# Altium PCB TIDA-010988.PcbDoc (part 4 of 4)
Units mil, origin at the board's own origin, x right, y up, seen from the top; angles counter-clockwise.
Board outline 3937.01 x 2559.06 mil, 4 copper layers (Top Layer, GND1, GND2, Bottom Layer), stack 61.6 mil thick; 270 components, 141 nets, 796 pads, 474 vias.
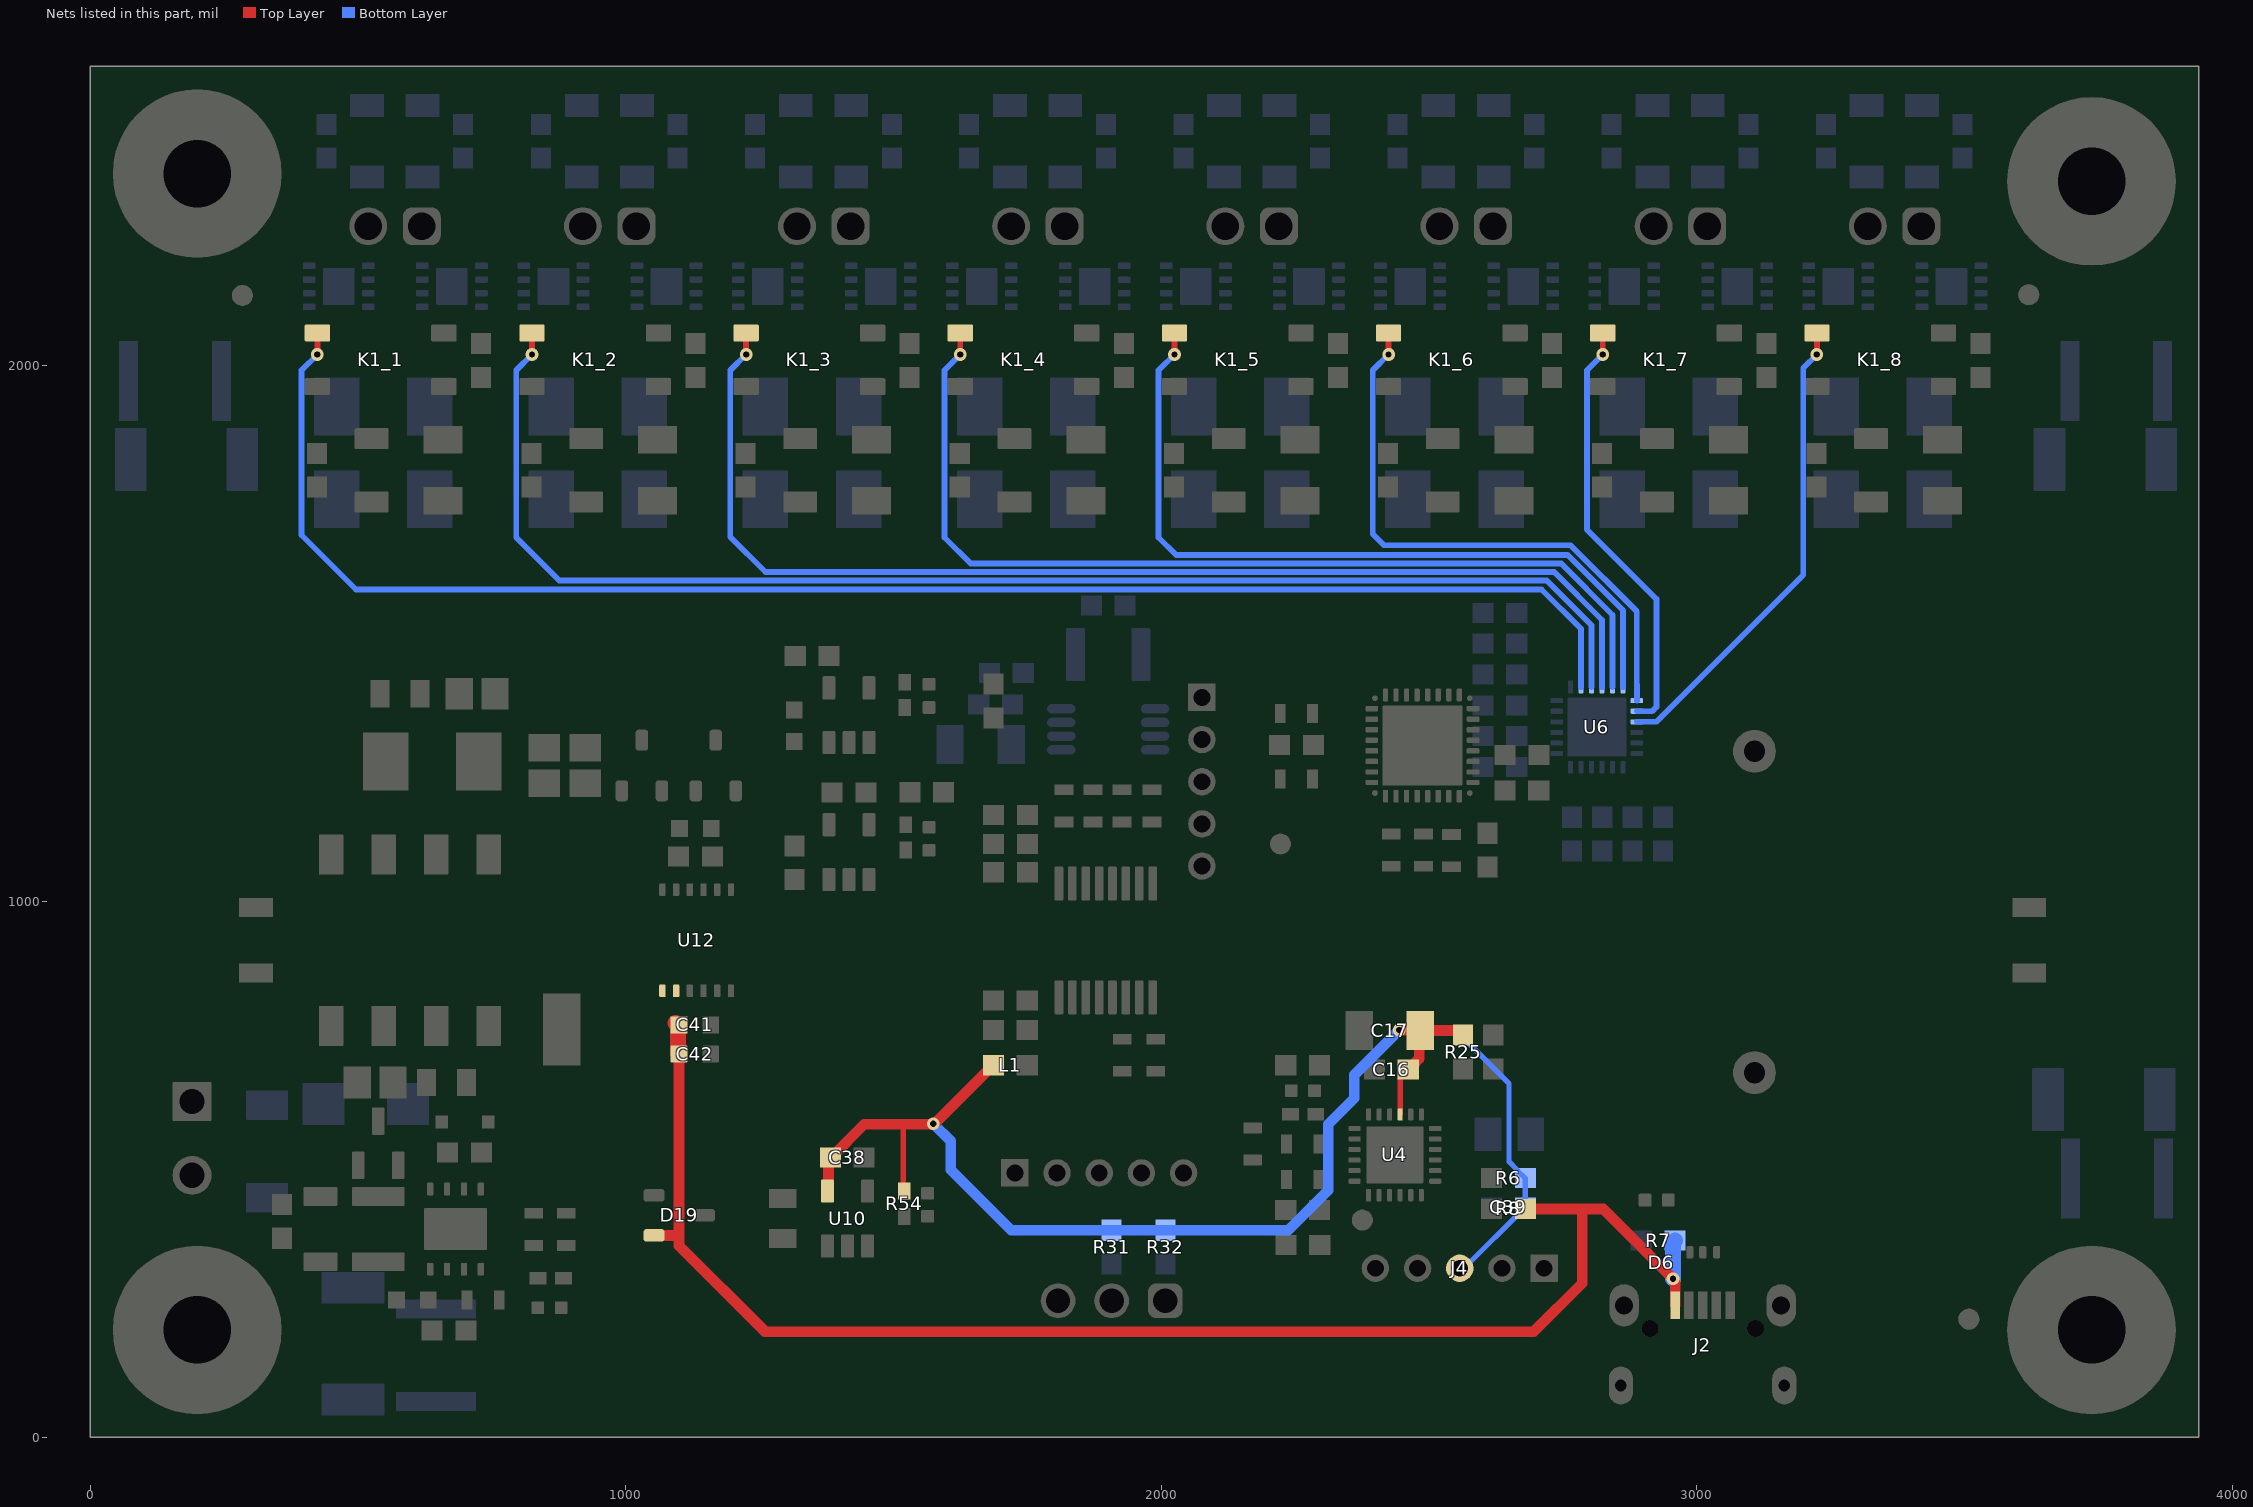
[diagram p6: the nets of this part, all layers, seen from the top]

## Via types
v1: diameter 23.62, hole 11.81, Top Layer to Bottom Layer, tented both sides, 374 vias
v2: diameter 19.68, hole 7.87, Top Layer to Bottom Layer, tented top, 64 vias
v3: diameter 19.68, hole 7.87, Top Layer to Bottom Layer, tented both sides, 26 vias
v4: diameter 19.68, hole 7.87, Top Layer to Bottom Layer, 9 vias
v5: diameter 28, hole 12, Top Layer to Bottom Layer, tented both sides, 1 vias

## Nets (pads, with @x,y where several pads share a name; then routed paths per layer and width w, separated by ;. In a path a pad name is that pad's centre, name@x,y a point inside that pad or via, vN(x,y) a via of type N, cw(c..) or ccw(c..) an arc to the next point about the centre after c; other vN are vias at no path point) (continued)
V/I_CTRL_1: K1_1.1 U6.20 | length 2959.5
  Top Layer w10.82: v1(424.4,2021.14) K1_1.1@424.4,2061.39
  Bottom Layer w10.82: v1(424.4,2021.14) 394.9,1991.64 394.9,1684.08 496.31,1582.67 2710.05,1582.67 2783.68,1509.04 U6.20@2783.68,1400.39
V/I_CTRL_2: K1_2.1 U6.21 | length 2585
  Top Layer w10.82: v1(825.02,2021.14) K1_2.1@825.02,2061.39
  Bottom Layer w10.82: v1(825.02,2021.14) 795.52,1991.64 795.52,1679.56 875.9,1599.18 2719.75,1599.18 2803.37,1515.56 U6.21@2803.37,1400.39
V/I_CTRL_3: K1_3.1 U6.22 | length 2210.1
  Top Layer w10.82: v1(1224.88,2021.14) K1_3.1@1224.88,2061.39
  Bottom Layer w10.82: v1(1224.88,2021.14) 1195.38,1991.64 1195.38,1680.53 1260.91,1615 2733.59,1615 2823.05,1525.54 U6.22@2823.05,1400.39
V/I_CTRL_4: K1_4.1 U6.23 | length 1836
  Top Layer w10.82: v1(1624.74,2021.14) K1_4.1@1624.74,2061.39
  Bottom Layer w10.82: v1(1624.74,2021.14) 1595.24,1991.64 1595.24,1679.74 1644.16,1630.82 2746.97,1630.82 2842.74,1535.05 U6.23@2842.74,1400.39
V/I_CTRL_5: K1_5.1 U6.24 | length 1460.6
  Top Layer w10.82: v1(2024.61,2021.14) K1_5.1@2024.61,2061.39
  Bottom Layer w10.82: v1(2024.61,2021.14) 1995.1,1991.64 1995.1,1679.41 2027.87,1646.64 2758.77,1646.64 2862.42,1542.99 U6.24@2862.42,1400.39
V/I_CTRL_6: K1_6.1 U6.1 | length 1103
  Top Layer w10.82: v1(2424.47,2021.14) K1_6.1@2424.47,2061.39
  Bottom Layer w10.82: v1(2424.47,2021.14) 2394.97,1991.64 2394.97,1685.91 2415.72,1665.16 2760.06,1665.16 ; 2764.26,1665.16 2887.82,1541.61 2887.82,1405.09 2888.01,1404.89 U6.1@2888.01,1374.8
V/I_CTRL_7: K1_7.1 U6.2 | length 804
  Top Layer w10.82: v1(2824.33,2021.14) K1_7.1@2824.33,2061.39
  Bottom Layer w10.82: v1(2824.33,2021.14) 2794.83,1991.64 2794.83,1694.2 2924.43,1564.59 2924.43,1363.01 2916.54,1355.12 U6.2@2888.01,1355.12
V/I_CTRL_8: K1_8.1 U6.3 | length 886.8
  Top Layer w10.82: v1(3224.19,2021.14) K1_8.1@3224.19,2061.39
  Bottom Layer w10.82: U6.3@2888.01,1335.43 2924.86,1335.43 3198.89,1609.46 3198.89,1995.84 v1(3224.19,2021.14)
VCC_3V3: C16.2 C17.2 C38.1 C39.1 J4.3 L1.1 R6.2 R25.1 R31.2 R32.2 R54.1 U4.3 U10.5 | length 2739.9
  Top Layer w10: R54.1@1517.97,459.18 1517.97,580.51 ; U4.3@2446.15,602.07 2446.15,671.95 C16.2@2460.14,685.94
  Top Layer w20: U10.5@1376.84,459.18 1378.65,460.99 C38.1@1378.65,517.89 ; C38.1@1382.2,521.67 1383.18,521.67 1445.71,584.2 1575.8,584.2 1685.78,694.17 L1.1@1686.76,694.17 ; v1(2444.46,759.99) 2492.38,759.99 C17.2@2493.4,758.98 ; C16.2@2460.14,685.94 C16.2@2460.81,686.62 ; C16.2@2470.81,695.63 2481.74,706.56 2481.74,747.33 C17.2@2493.4,758.98 ; R25.1@2563.63,750.28 2554.93,758.98 C17.2@2493.4,758.98
  Bottom Layer w10: v1(2444.46,759.99) 2549.34,759.99 2649.2,660.13 2649.2,514.11 2665.16,498.15 2665.16,497.17 2678.86,483.47 R6.2@2679.84,483.47 C39.1@2679.84,428.8 2678.86,428.8 2565.16,315.11 J4.3@2557.32,315.11
  Bottom Layer w20: v1(1574.47,585.12) 1606.88,552.71 1606.88,499.27 1720.07,386.08 R31.2@1907.36,386.08 R32.2@2007.75,386.08 2237.28,386.08 2311.98,460.79 2311.98,584.14 2360.48,632.64 2360.48,676.02 v1(2444.46,759.99)
VUSB: C41.2 C42.2 D6.2 D19.2 J2.1 R7.2 R8.2 U12.1 U12.2 | length 2857.5
  Top Layer w10: C41.2@1094.2,772.18 C41.2@1096.82,769.55
  Top Layer w15: v1(2955.37,295.75) 2955.37,293.42 v1@2959.62,289.17
  Top Layer w20: D19.2@1044.44,377.49 D19.2@1052.32,377.49 ; D19.2@1052.83,376.45 1098.74,376.45 1099.77,377.49 ; C42.2@1097.81,715.09 1099.77,713.12 1099.77,377.49 ; R8.2@2679.84,425.9 2786.03,425.9 ; v1(2955.37,295.75) 2825.23,425.9 2786.03,425.9 ; J2.1@2959.62,245.88 v1@2959.62,289.17 ; 1099.77,377.49 1099.77,357.05 1260,196.82 2695.72,196.82 2786.03,287.14 2786.03,425.9
  Top Layer w30: C41.2@1093.12,773.26 C41.2@1094.2,772.18 ; C41.2@1096.82,769.55 1097.81,769.55 C42.2@1097.81,715.09
  Bottom Layer w30: v1(2955.37,295.75) 2955.37,363.21 2959.07,366.91 R7.2@2959.25,366.91
pads on no net: D4.1S D4.2S D5.1S D5.2S D6.1S D6.2S D10.2 FID1.1 FID2.1 FID3.1 FID4.1 FID5.1 FID6.1 H5.0 H6.0 H7.0 H8.0 J2. LBL1.0 T1.2 T1.3 U1_1.9 U1_2.9 U1_3.9 U1_4.9 U1_5.9 U1_6.9 U1_7.9 U1_8.9 U2_1.9 U2_2.9 U2_3.9 U2_4.9 U2_5.9 U2_6.9 U2_7.9 U2_8.9 U4.11 U4.12 U4.13 U4.17 U6.4 U6.5 U6.6 U6.7 U6.8 U8.9@652.55,388.27 U8.9@712,388.27 U9.4 U10.3 U10.4 U11.3 U11.4
copper on no net:
  other v2: 464.53,2123.71 675.61,2123.71 865.15,2123.71 1076.23,2123.71 1265.01,2123.71 1476.09,2123.71 1664.87,2123.71 1875.95,2123.71 2064.73,2123.71 2275.82,2123.71 2464.59,2123.71 2675.68,2123.71 2864.45,2123.71 3075.54,2123.71 3264.32,2123.71 3475.4,2123.71 444.84,2148.32 484.21,2148.32 655.93,2148.32 695.3,2148.32 845.46,2148.32 884.83,2148.32 1056.55,2148.32 1095.92,2148.32 1245.32,2148.32 1284.69,2148.32 1456.41,2148.32 1495.78,2148.32 1645.19,2148.32 1684.56,2148.32 1856.27,2148.32 1895.64,2148.32 2045.05,2148.32 2084.42,2148.32 2256.13,2148.32 2295.5,2148.32 2444.91,2148.32 2484.28,2148.32 2655.99,2148.32 2695.36,2148.32 2844.77,2148.32 2884.14,2148.32 3055.85,2148.32 3095.22,2148.32 3244.63,2148.32 3284,2148.32 3455.72,2148.32 3495.09,2148.32 464.53,2172.93 675.61,2172.93 865.15,2172.92 1076.23,2172.92 1265.01,2172.92 1476.09,2172.92 1664.87,2172.92 1875.95,2172.92 2064.73,2172.92 2275.82,2172.92 2464.59,2172.92 2675.68,2172.92 2864.45,2172.92 3075.54,2172.92 3264.32,2172.92 3475.4,2172.92

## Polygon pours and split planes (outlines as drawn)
GND on Top Layer "TOP_LAYER_GND_P188" (solid, remove dead copper, pour order 188): 1150.98,1011.08 1100.2,1011.03 1049.51,1011.08 1049.51,1155.81 1121.25,1155.81 1121.37,1155.68 1121.37,1050.28 1137.55,1034.11 1151.31,1034.11
GND_0V on Top Layer "TOP_LAYER_GND_0V_P187" (solid, remove dead copper, pour order 187): 1113.9,845 1113.9,822.42 1113.87,822.39 1113.9,822.35 1113.9,805.3 1114.03,805.3 1124.93,794.4 1125.14,794.61 1140.58,794.61 1140.58,696.68 1140.43,696.53 1140.56,696.4 1181.79,696.4 1211.64,696.4 1211.64,844.91 1203.85,844.92
VUSB on Top Layer "TOP_LAYER_VUSB_P186" (solid, remove dead copper, pour order 186): 1099.95,844.87 1062.82,844.87 1062.67,845.02 1062.49,844.84 1062.49,695.23 1117.66,695.23 1117.66,787.67 1112.44,792.9 1100.09,805.25
NetD1_1_2 on Top Layer "TOP_LAYER_NETD1_1_2_P142" (solid, remove dead copper, pour order 142): 650.1,1858.84 648.89,1860.06 648.89,1976.62 749.09,1976.62 749.09,1896.19
NetD1_3_2 on Top Layer "TOP_LAYER_NETD1_3_2_P144" (solid, remove dead copper, pour order 144): 1450.58,1858.84 1449.37,1860.06 1449.37,1976.62 1549.57,1976.62 1549.57,1896.19
NetD1_8_2 on Top Layer "TOP_LAYER_NETD1_8_2_P149" (solid, remove dead copper, pour order 149): 3449.89,1858.84 3448.68,1860.06 3448.68,1976.62 3548.87,1976.62 3548.87,1896.19
NetD1_7_2 on Top Layer "TOP_LAYER_NETD1_7_2_P148" (solid, remove dead copper, pour order 148): 3050.03,1858.84 3048.81,1860.06 3048.81,1976.62 3149.01,1976.62 3149.01,1896.19
NetD1_6_2 on Top Layer "TOP_LAYER_NETD1_6_2_P147" (solid, remove dead copper, pour order 147): 2650.17,1858.84 2648.95,1860.06 2648.95,1976.62 2749.15,1976.62 2749.15,1896.19
NetD1_5_2 on Top Layer "TOP_LAYER_NETD1_5_2_P146" (solid, remove dead copper, pour order 146): 2250.31,1858.84 2249.09,1860.06 2249.09,1976.62 2349.29,1976.62 2349.29,1896.19
NetD1_4_2 on Top Layer "TOP_LAYER_NETD1_4_2_P145" (solid, remove dead copper, pour order 145): 1850.45,1858.84 1849.23,1860.06 1849.23,1976.62 1949.43,1976.62 1949.43,1896.19
NetD1_2_2 on Top Layer "TOP_LAYER_NETD1_2_2_P143" (solid, remove dead copper, pour order 143): 1050.72,1858.84 1049.51,1860.06 1049.51,1976.62 1149.7,1976.62 1149.7,1896.19
GND on Bottom Layer "BOTTOM_LAYER_GND_P190" (solid, remove dead copper, pour order 190): 3737.09,2050.14 3737.09,1774.96 3737.09,1765.76 3666.35,1765.76 3595.51,1765.76 3594.27,1765.76 3594.27,1769.02 3594.27,1777.29 3594.27,2049.84
GND_0V on Bottom Layer "BOTTOM_LAYER_GND_0V_P193" (solid, remove dead copper, pour order 193): 721.27,201.89 446.35,201.89 428.91,201.89 428.91,344.71 440.4,344.71 448.68,344.71 720.96,344.71
GND_0V on Bottom Layer "BOTTOM_LAYER_GND_0V_P192" (solid, remove dead copper, pour order 192): 3626.86,690.15 3626.86,414.64 3626.86,405.44 3697.6,405.44 3768.44,405.44 3769.68,405.44 3769.68,408.7 3769.68,416.97 3769.68,689.85
GND on Bottom Layer "BOTTOM_LAYER_GND_P191" (solid, remove dead copper, pour order 191): 204.2,2050.16 204.2,1774.96 204.2,1765.76 274.94,1765.76 345.78,1765.76 347.02,1765.76 347.02,1769.02 347.02,1777.29 347.02,2049.86
GND on Bottom Layer "BOTTOM_LAYER_GND_P150" (solid, remove dead copper, pour order 150): 415.91,2201.46 421.66,2195.71 421.67,2107.21 416.5,2102.04 379.59,2102.04 368.18,2116.64 368.18,2193.81 379.75,2201.39
GND on Bottom Layer "BOTTOM_LAYER_GND_P158" (solid, remove dead copper, pour order 158): 721.71,2103.98 715.95,2109.73 715.94,2198.22 721.12,2203.4 758.02,2203.4 771.4,2203.4 771.4,2190.01 771.4,2104.08 757.87,2104.05
GND on Bottom Layer "BOTTOM_LAYER_GND_P184" (solid, remove dead copper, pour order 184): 3215.5,2203.1 3221.25,2197.35 3221.26,2108.86 3216.09,2103.68 3179.19,2103.68 3167.77,2103.68 3167.77,2118.29 3167.77,2195.46 3167.77,2203.1 3179.34,2203.03
GND on Bottom Layer "BOTTOM_LAYER_GND_P183" (solid, remove dead copper, pour order 183): 3123.43,2103.86 3117.68,2109.62 3117.67,2198.11 3122.84,2203.28 3159.74,2203.28 3173.13,2203.28 3173.13,2189.9 3173.13,2117.47 3173.13,2103.86 3159.59,2103.94
GND on Bottom Layer "BOTTOM_LAYER_GND_P182" (solid, remove dead copper, pour order 182): 2815.64,2203.1 2821.39,2197.35 2821.4,2108.86 2816.23,2103.68 2779.32,2103.68 2767.91,2103.68 2767.91,2118.29 2767.91,2195.46 2767.91,2203.1 2779.48,2203.03
GND on Bottom Layer "BOTTOM_LAYER_GND_P181" (solid, remove dead copper, pour order 181): 2723.57,2103.86 2717.81,2109.62 2717.8,2198.11 2722.98,2203.28 2759.88,2203.28 2773.26,2203.28 2773.26,2189.9 2773.26,2117.47 2773.26,2103.86 2759.73,2103.94
GND on Bottom Layer "BOTTOM_LAYER_GND_P180" (solid, remove dead copper, pour order 180): 2415.78,2203.1 2421.53,2197.35 2421.54,2108.86 2416.37,2103.68 2379.46,2103.68 2368.05,2103.68 2368.05,2118.29 2368.05,2195.46 2368.05,2203.1 2379.62,2203.03
GND on Bottom Layer "BOTTOM_LAYER_GND_P179" (solid, remove dead copper, pour order 179): 2323.71,2103.86 2317.95,2109.62 2317.94,2198.11 2323.12,2203.28 2360.02,2203.28 2373.4,2203.28 2373.4,2189.9 2373.4,2117.47 2373.4,2103.86 2359.87,2103.94
GND on Bottom Layer "BOTTOM_LAYER_GND_P178" (solid, remove dead copper, pour order 178): 2015.92,2203.1 2021.67,2197.35 2021.68,2108.86 2016.51,2103.68 1979.6,2103.68 1968.19,2103.68 1968.19,2118.29 1968.19,2195.46 1968.19,2203.1 1979.76,2203.03
GND on Bottom Layer "BOTTOM_LAYER_GND_P177" (solid, remove dead copper, pour order 177): 1923.84,2103.86 1918.09,2109.62 1918.08,2198.11 1923.25,2203.28 1960.16,2203.28 1973.54,2203.28 1973.54,2189.9 1973.54,2117.47 1973.54,2103.86 1960.01,2103.94
GND on Bottom Layer "BOTTOM_LAYER_GND_P176" (solid, remove dead copper, pour order 176): 1616.06,2203.1 1621.81,2197.35 1621.82,2108.86 1616.65,2103.68 1579.74,2103.68 1568.33,2103.68 1568.33,2118.29 1568.33,2195.46 1568.33,2203.1 1579.89,2203.03
GND on Bottom Layer "BOTTOM_LAYER_GND_P175" (solid, remove dead copper, pour order 175): 1523.98,2103.86 1518.23,2109.62 1518.22,2198.11 1523.39,2203.28 1560.3,2203.28 1573.68,2203.28 1573.68,2189.9 1573.68,2117.47 1573.68,2103.86 1560.14,2103.94
GND on Bottom Layer "BOTTOM_LAYER_GND_P172" (solid, remove dead copper, pour order 172): 1216.19,2203.1 1221.95,2197.35 1221.96,2108.86 1216.78,2103.68 1179.88,2103.68 1168.47,2103.68 1168.47,2118.29 1168.47,2195.46 1168.47,2203.1 1180.03,2203.03
GND on Bottom Layer "BOTTOM_LAYER_GND_P171" (solid, remove dead copper, pour order 171): 820.53,2203.1 826.29,2197.35 826.3,2108.86 821.12,2103.68 784.22,2103.68 772.81,2103.68 741.02,2103.68 741.02,2161.33 741.02,2203.3 742.92,2203.1 772.81,2203.1 784.37,2203.03
GND on Bottom Layer "BOTTOM_LAYER_GND_P165" (solid, remove dead copper, pour order 165): 3520.32,2103.64 3514.57,2109.39 3514.56,2197.88 3519.73,2203.06 3556.63,2203.06 3570.02,2189.67 3570.02,2117.25 3556.48,2103.71
GND on Bottom Layer "BOTTOM_LAYER_GND_P159" (solid, remove dead copper, pour order 159): 1124.12,2103.86 1118.37,2109.62 1118.36,2198.11 1123.53,2203.28 1160.44,2203.28 1173.82,2203.28 1173.82,2189.9 1173.82,2117.47 1173.82,2103.86 1160.28,2103.94
GND on GND1 "GND1_GND_P167" (solid, remove dead copper, pour order 167): -3.37,972.72 -3.37,2553.11 3933.64,2553.11 3933.64,972.72
GND_0V on GND1 "GND1_GND_0V_P168" (solid, remove dead copper, pour order 168): 0,883.66 0,0 3937.01,0 3937.01,883.66
GND on GND2 "GND2_GND_P166" (solid, remove dead copper, pour order 166): 0,972.72 0,2559.06 3937.01,2559.06 3937.01,972.72
GND_0V on GND2 "GND2_GND_0V_P169" (solid, remove dead copper, pour order 169): -0.01,883.66 -0.01,-4 3937,-4 3937,883.66

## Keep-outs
Keep-Out Layer:
  text ".Layer_Name" at 132,-1764.01 h60

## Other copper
Top Layer:
  text ".Layer_Name" at 132,-1764.01 h60
Bottom Layer:
  text ".Layer_Name" at 132,-1764.01 h60

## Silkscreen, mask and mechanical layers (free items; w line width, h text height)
Top Overlay:
  lines w5: 2037,1445.84 2037,1446.25
  lines w8: 1586.46,190.64 1586.46,486.09 1657.68,486.09
  lines w10: 1641.21,502.3 1657.39,486.11 ; 1641.49,469.9 1657.68,486.09 ; 2020.78,1462.97 2036.97,1446.78 ; 2037,1445.84 2037,1654.07 ; 2037,1446.04 2037,1446.5 2053.19,1462.69
  text "A14" at 3094.45,2279.92 h30
  text "A10" at 703.23,2251.04 h30
  text "A8" at 1104.3,2251.08 h30
  text "A6" at 1504.42,2251.04 h30
  text "A4" at 1905.27,2251.06 h30
  text "A3" at 1995.82,2251.23 h30
  text "A2" at 2304.44,2251.1 h30
  text "A0" at 2704.16,2251.14 h30
  text "A15" at 2769.16,2251.71 h30
  text "A11" at 374.18,2250.96 h30
  text "A9" at 798.31,2250.96 h30
  text "A7" at 1192.94,2250.96 h30
  text "A5" at 1596.27,2250.89 h30
  text "A1" at 2399.24,2250.96 h30
  text "A13" at 3172.29,2243.59 h30
  text "A12" at 3494.87,2202.36 h30
  text "CSADC" at 2049.25,1608 h70
  text "SCLK" at 2049.25,1554.91 h70
  text "SDI" at 2049.25,1501.42 h70
  text "SDO" at 2054.3,1439.46 h70
  text "CS IO" at 2023.65,968.38 h70
  text "24V" at 139.91,715.09 h100
  text "CSADC" at 1597.33,396.74 h70
  text "GND" at 29.06,353.3 h70
  text "GND_0V" at 1597.33,343.71 h70
  text "SCLK" at 1597.33,276.91 h70
  text "PICO" at 1597.33,225.18 h70
  text "POCI" at 1597.33,172.22 h70
  text "RX" at 1878.46,140 h70
  text "TX" at 1977.83,140 h70
  text "RST" at 2747.33,110.96 h70 r90
  text "SWDIO" at 2424.65,60 h70 r90
  text "TIDA-010988.PCB_Rev" at 361.59,50 h108.27
  text "SWCLK" at 2500.3,46.65 h70 r90
  text "VCC3V3" at 2578.56,25.92 h70 r90
  text "GND_0V" at 2662.99,20 h70 r90
  text ".Layer_Name" at 132,-1764.01 h60
Bottom Overlay:
  text ".Layer_Name" at 132,-1764.01 h60
Top Paste:
  text ".Layer_Name" at 132,-1764.01 h60
Bottom Paste:
  text ".Layer_Name" at 132,-1764.01 h60
Top Solder:
  text ".Layer_Name" at 132,-1764.01 h60
  text ".Layer_Name" at 132,-1764.01 h60
Bottom Solder:
  text ".Layer_Name" at 132,-1764.01 h60
Drill Guide:
  text ".Layer_Name" at 132,-1764.01 h60
M1 Board Outline:
  the board outline again, w10
  text ".Layer_Name" at 132,-1764.01 h60
M2 Board Dimensions:
  rectangle: -445,-1180.51 -320,-1055.51
  rectangle: -320,-1305.51 55,-1180.51
  lines w7: -445,-1180.51 555,-1180.51 ; -320,-1305.51 -320,-1055.51 ; -195,-1305.51 -195,-1055.51 ; 55,-1305.51 55,-1055.51 ; 305,-1305.51 305,-1055.51 ; -445,-1305.51 555,-1305.51 555,-1055.51 -445,-1055.51 -445,-1305.51
  text ".Layer_Name" at 132,-1764.01 h60
M3 3D STEP Top:
  text ".Layer_Name" at 132,-1764.01 h60
M4 3D STEP Bottom:
  text ".Layer_Name" at 132,-1764.01 h60
M5 Assembly Top:
  lines w10: -737,-1835.68 5863,-1835.68 ; -737,-1632.35 5865,-1632.35 ; -737,-1429.01 -737,-2039.01 3268,-2039.01 5865,-2039.01 5865,-1429.01 -736.5,-1429.01 -736.5,-2039.01 839,-2039.01 ; 1728,-2039.01 1728,-1429.01 ; 2995,-1632.35 2995,-1429.01 ; 3835,-1632.35 3835,-1429.01 ; 4457,-2045.51 4457,-1842.68
  text "COMPONENTS MARKED 'DNP' SHOULD NOT BE POPULATED." at 708.5,-1224.01 h60
  text "ASSEMBLY VARIANT:" at 708,-1339.51 h60
  text ".VariantName" at 1744,-1339.51 h60
  text "PCB VIEWED FROM TOP SIDE" at -673.5,-1561.18 h60
  text "BOARD #:" at 1803,-1561.18 h60
  text ".PRJ_Number" at 2348.5,-1561.18 h60
  text "REV:" at 3193,-1561.18 h60
  text ".PCB_Rev" at 3484.5,-1561.18 h60
  text "SVN REV:" at 4031,-1561.18 h60
  text ".VersionControl_RevNumber" at 4537,-1561.18 h60
  text "TID #:" at 1803,-1764.51 h60
  text ".TID" at 2348.5,-1764.51 h60
  text "PLOT NAME =" at -673.5,-1969.85 h60
  text ".plot_File_Name" at 132,-1969.85 h60
  text "GENERATED    :" at 1805,-1969.85 h60
  text ".Print_Date" at 2674.5,-1969.85 h60
  text ".Print_Time" at 3403.5,-1969.85 h60
  text "TEXAS INSTRUMENTS" at 4668,-1969.85 h60
M6 Assembly Bottom:
  lines w10: -737.5,-1632.85 5864.5,-1632.85 ; -735.5,-1836.18 5864.5,-1836.18 ; 670.5,-2046.01 670.5,-1843.18 ; 1292.5,-1632.85 1292.5,-1429.51 ; 2132.5,-1632.85 2132.5,-1429.51 ; 3399.5,-2039.51 3399.5,-1429.51 ; 4288.5,-2039.51 5864,-2039.51 5864,-1429.51 -737.5,-1429.51 -737.5,-2039.51 1859.5,-2039.51 5864.5,-2039.51 5864.5,-1429.51
  text "COMPONENTS MARKED 'DNP' SHOULD NOT BE POPULATED." at 5657,-1223.51 h60
  text ".VariantName" at 4613,-1339.51 h60
  text "ASSEMBLY VARIANT:" at 5652,-1339.51 h60
  text ".VersionControl_RevNumber" at 590.5,-1561.68 h60
  text "SVN REV:" at 1096.5,-1561.68 h60
  text ".PCB_Rev" at 1643,-1561.68 h60
  text "REV:" at 1934.5,-1561.68 h60
  text ".PRJ_Number" at 2779,-1561.68 h60
  text "BOARD #:" at 3324.5,-1561.68 h60
  text "PCB VIEWED FROM BOTTOM SIDE" at 5801,-1561.68 h60
  text ".TID" at 2779,-1765.01 h60
  text "TID #:" at 3324.5,-1765.01 h60
  text "TEXAS INSTRUMENTS" at 459.5,-1970.35 h60
  text ".Print_Time" at 1724,-1970.35 h60
  text ".Print_Date" at 2453,-1970.35 h60
  text "GENERATED    :" at 3322.5,-1970.35 h60
  text ".plot_File_Name" at 4995.5,-1970.35 h60
  text "PLOT NAME =" at 5801,-1970.35 h60
M9 Title Sheet:
  drawing of 57 lines, arcs and shapes, not listed
  text "1" at 294.84,7130.99 h70
  text "2" at 2790.5,7130.99 h70
  text "3" at 5279.84,7130.99 h70
  text "4" at 7786.51,7130.99 h70
  text "5" at 10285.5,7130.99 h70
  text "6" at 12790.5,7130.99 h70
  text "A" at -861.5,5987.99 h70
  text "A" at 13938.5,5987.99 h70
  text "B" at -861.5,3607.99 h70
  text "B" at 13938.5,3607.99 h70
  text "C" at -861.5,1232.99 h70
  text "C" at 13938.5,1232.99 h70
  text "PROJECT TITLE:" at 10898.5,-628.01 h45
  text ".PRJ_Title" at 10948.5,-761.34 h70
  text "DESIGNED FOR:" at 10898.5,-929.01 h45
  text ".PRJ_Customer" at 10948.5,-1069.01 h70
  text "D" at -861.5,-1137.01 h70
  text "D" at 13938.5,-1137.01 h70
  text "FILE NAME:" at 10898.5,-1229.01 h45
  text ".PCB_File_Name_No_Path" at 10948.5,-1349.01 h70
  text "Texas Instruments (TI) and/or its licensors do not warrant the accuracy or completeness of this specification" at 5929,-1510.85 h45
  text "ENGINEER:" at 10898.5,-1519.01 h45
  text "LAYOUT BY:" at 12403.5,-1519.01 h45
  text "or any information contained therein. TI and/or its licensors do not warrant that this design will meet" at 5884.01,-1623.52 h45
  text ".PRJ_Engineer" at 10948.5,-1674 h70
  text ".PCB_Layout" at 12454,-1674 h70
  text "the specifications, will be suitable for your application or fit for any particular purpose, or will operate in" at 5884.01,-1736.18 h45
  text ".Layer_Name" at 132,-1764.01 h60
  text "ALTIUM DESIGNER VERSION:" at 12403.5,-1829.01 h45
  text "an implementation. TI and/or its licensors do not warrant that the design is production worthy. You should" at 5884.01,-1848.85 h45
  text "completely validate and test your design implementation to confirm the system functionality for your application." at 5929,-1961.51 h45
  text ".print_Scale" at 10948.5,-1962.34 h70
  text ".Application_BuildNumber" at 12454,-1962.34 h70
  text "1" at 294.84,-2169.01 h70
  text "2" at 2790.5,-2169.01 h70
  text "3" at 5279.84,-2169.01 h70
  text "4" at 7786.51,-2169.01 h70
  text "5" at 10285.5,-2169.01 h70
  text "6" at 12790.5,-2169.01 h70
M10 Fab Notes:
  drawing of 189 lines, arcs and shapes, not listed
  text "DESIGN INFORMATION" at 11937.02,5450.66 h60
  text "MIN. TRACK WIDTH:" at 11292.46,5318.54 h60
  text "8" at 12388.7,5318.54 h60
  text "MIL" at 12543.46,5318.54 h60
  text "7.874" at 12222.32,5196.85 h60
  text "MIN. CLEARANCE:" at 11292.46,5194.41 h60
  text "MIL" at 12543.46,5194.41 h60
  text "MIN. VIA PAD SIZE:" at 11292.46,5070.28 h60
  text "24" at 12358.71,5070.29 h60
  text "MIL" at 12543.46,5070.28 h60
  text "0.05mm (2MIL)" at 11987.46,4940.38 h60
  text "MINIMUM ANNULAR RING" at 10963.23,4932.16 h60
  text "EXTERNAL" at 12695.46,4932.16 h60
  text "PER" at 11163.23,4822.04 h60
  text "IPC-D-275 CLASS 2 LEVEL C" at 11383.23,4822.03 h60
  text "MIL, HOLES" at 12871.46,4721.56 h60
  text "+/-" at 12479,4712.97 h60
  text "+/-" at 13333,4712.97 h60
  text "REGISTRATION TOLERANCES:" at 10963.23,4711.91 h60
  text "METAL" at 12163,4711.91 h60
  text "5" at 12739.2,4711.91 h60
  text "3" at 13572.2,4711.91 h60
  text "MIL" at 13688.46,4711.91 h60
  text "HOLE SIZE TOLERANCE (UNLESS OTHERWISE SPECIFIED):" at 10963.23,4613.59 h60
  text "+/-" at 13333,4610.72 h60
  text "3" at 13572.2,4609.66 h60
  text "MIL" at 13688.46,4609.65 h60
  text "MATERIAL:" at 10888.46,4472.01 h60
  text "FR-4 High Tg" at 11874.9,4343.48 h60
  text "X" at 11730.46,4335.49 h60
  text "FR-4" at 11309.46,4330.98 h60
  text "OTHER" at 12797.46,4330.98 h60
  text "62 MIL (1.6mm) +/-10%" at 11629.56,4187.95 h60
  text "X" at 11509.46,4185.49 h60
  text "THICKNESS:" at 10963.23,4179.73 h60
  text "OTHER" at 12914.46,4179.73 h60
  text "TOLERANCE:" at 10963.23,4041.41 h60
  text "X" at 11811.46,4041.41 h60
  text "ANSI IPC-6012 TYPE 3 CLASS 2" at 11989.48,4041.41 h60
  text "OTHER +/-" at 11989.46,3897.22 h60
  text "BOW & TWIST:" at 10963.23,3752.03 h60
  text "X" at 11811.46,3752.03 h60
  text "ANSI IPC-6012 TYPE 3 CLASS 2" at 11989.48,3752.03 h60
  text "OTHER +/-" at 11989.46,3605.34 h60
  text "DRILLING:" at 10888.46,3474.72 h60
  text "NC_DRILL FILES" at 12649.46,3369.53 h60
  text "REFERENCE:" at 10963.23,3365.59 h60
  text "X" at 11620.46,3365.49 h60
  text "AS SHOWN" at 11798.46,3365.59 h60
  text "X" at 12521.46,3365.59 h60
  text "OTHER" at 12947.46,3223.34 h60
  text "PTH COPPER THICKNESS:" at 10962.91,3219.81 h60
  text "X" at 12102.14,3219.81 h60
  text "20-30 um" at 12230.14,3219.81 h60
  text "BOARD FINISH:" at 10888.46,3072.21 h60
  text "SILKSCREEN:" at 11043.68,2962.09 h60
  text "X" at 12001.46,2962.09 h60
  text "TOP" at 12118.46,2962.09 h60
  text "X" at 12511.46,2962.09 h60
  text "BOTTOM" at 12629.46,2962.09 h60
  text "SILKSCREEN COLOR:" at 11043.68,2806.9 h60
  text "X" at 12000.46,2806.9 h60
  text "WHITE" at 12118.46,2806.9 h60
  text "OTHER" at 12629.46,2806.9 h60
  text "X" at 12131.46,2663.45 h60
  text "GREEN" at 12249.46,2663.45 h60
  text "OTHER" at 12867.46,2663.45 h60
  text "SOLDER RESIST COLOR:" at 11043.68,2656.58 h60
  text "X" at 12131.46,2509.2 h60
  text "MATTE" at 12249.46,2509.2 h60
  text "SEMI-GLOSS" at 12867,2508.56 h60
  text "IMMERSION GOLD (ENIG)" at 11949.46,2336.43 h60
  text "ENEPIG" at 13287,2329.21 h60
  text "SURFACE FINISH:" at 10888.46,2328.21 h60
  text "X" at 11771.46,2328.21 h60
  text "IMM. TIN/SILVER OR EQUIV" at 11218,2190.89 h60
  text "OTHER" at 12649.46,2186.95 h60
  text "ARRAY/PANEL:" at 10888.46,2031.58 h60
  text "CUT AND TRIM PER M1 BOARD OUTLINE" at 11949.46,2023.35 h60
  text "N.C. ROUTE" at 11949.46,1887.39 h60
  text "X" at 12637.46,1887.39 h60
  text "V. SCORE" at 12815.46,1887.39 h60
  text "CERTIFICATION:" at 10888.46,1758.26 h60
  text "MATERIALS AND WORKMANSHIP FOR ALL PCBS" at 11613.46,1758.26 h60
  text "TO MEET OR EXCEED THE REQUIREMENTS OF:" at 11613.46,1664.2 h60
  text "X" at 11250.97,1535.57 h60
  text "ANSI IPC-A-600F CLASS ->" at 11378.96,1535.57 h60
  text "X" at 13026.97,1535.57 h60
  text "2" at 13136.96,1535.57 h60
  text "1" at 12821.96,1534.07 h60
  text "3" at 13490.96,1534.07 h60
  text "X" at 12062.97,1387.88 h60
  text "RoHS" at 12190.96,1387.88 h60
  text "OTHER" at 12835.36,1387.88 h60
  text "PER ORDER" at 13232.42,1387.88 h60
  text "ALL BOARDS MUST MEET OR EXCEED UL94-V0 REQUIREMENTS." at 10916,1234.06 h60
  text "PCB MUST BEAR THE UL94V-0 UL REGISTERED MATERIAL ID NUMBER" at 10916,1117.99 h60
  text "ADDITIONAL REQUIREMENTS:" at 10888.46,948.57 h60
  text "MICROSECTION:" at 10963.23,841.44 h60
  text "YES" at 11868.96,841.44 h60
  text "REQUIRED" at 12730.46,697.11 h60
  text "BARE BOARD ELEC. TEST:" at 10963.23,694.25 h60
  text "NONE" at 12268.96,694.25 h60
  text "X" at 12612.46,694.25 h60
  text "PER ORDER" at 13322.46,694.25 h60
  text "XX MIL VIAS REQUIRE NON-CONDUCTIVE FILL AND PLANARIZE" at 11131.38,489.31 h59
  text "XX MIL VIAS REQUIRE CONDUCTIVE FILL AND PLANARIZE" at 11139.38,385.33 h60
  text "OUTER XX MIL TRACES REQUIRE 50 OHM SINGLE-ENDED IMPEDANCE" at 11138.39,221.95 h58
  text "LAYER 2 & 3 (INNER LAYERS) XX MIL WIDE, XX MIL SPACE / TRACES REQUIRE 100 OHM DIFFERENTIAL IMPEDANCE" at 11130.39,-13.77 h60
  text ".Layer_Name" at 132,-1764.01 h60
M11 Gerber Information:
  lines w10: -737,-1835.68 5863,-1835.68 ; -737,-1632.35 5865,-1632.35 ; -737,-1429.01 -737,-2039.01 3268,-2039.01 5865,-2039.01 5865,-1429.01 -736.5,-1429.01 -736.5,-2039.01 839,-2039.01 ; 1728,-2039.01 1728,-1429.01 ; 2995,-1632.35 2995,-1429.01 ; 3835,-1632.35 3835,-1429.01 ; 4457,-2045.51 4457,-1842.68
  text "ALL ARTWORK VIEWED FROM TOP SIDE" at -673.5,-1561.18 h60
  text "BOARD #:" at 1803,-1561.18 h60
  text ".PRJ_Number" at 2348.5,-1561.18 h60
  text "REV:" at 3193,-1561.18 h60
  text ".PCB_Rev" at 3484.5,-1561.18 h60
  text "SVN REV:" at 4031,-1561.18 h60
  text ".VersionControl_RevNumber" at 4537,-1561.18 h60
  text "LAYER NAME =" at -673.5,-1764.01 h60
  text "TID #:" at 1803,-1764.51 h60
  text ".TID" at 2348.5,-1764.51 h60
  text "PLOT NAME =" at -673.5,-1969.85 h60
  text ".plot_File_Name" at 132,-1969.85 h60
  text "GENERATED    :" at 1805,-1969.85 h60
  text ".Print_Date" at 2674.5,-1969.85 h60
  text ".Print_Time" at 3403.5,-1969.85 h60
  text "TEXAS INSTRUMENTS" at 4668,-1969.85 h60
M12 Stackup:
  text ".Layer_Name" at 132,-1764.01 h60
M13 Component Bodies Top:
  text ".Layer_Name" at 132,-1764.01 h60
M14 Component Bodies Bottom:
  text ".Layer_Name" at 132,-1764.01 h60
M15 Courtyards Top:
  text ".Layer_Name" at 132,-1764.01 h60
M16 Courtyards Bottom:
  text ".Layer_Name" at 132,-1764.01 h60
Drill Drawing:
  text ".Layer_Name" at 132,-1764.01 h60
M17 Embedded Cavity:
  text ".Layer_Name" at 132,-1764.01 h60
M18 Embedded Assembly:
  text ".Layer_Name" at 132,-1764.01 h60
M19 Embedded Keepout:
  text ".Layer_Name" at 132,-1764.01 h60

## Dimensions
0,2559.06 to 0,0 on M2 Board Dimensions
0,0 to 3937.01,0 on M2 Board Dimensions
-445,-905.51 to 0,2559.06 on M2 Board Dimensions
-445,-1305.51 to 555,-1305.51 on M2 Board Dimensions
